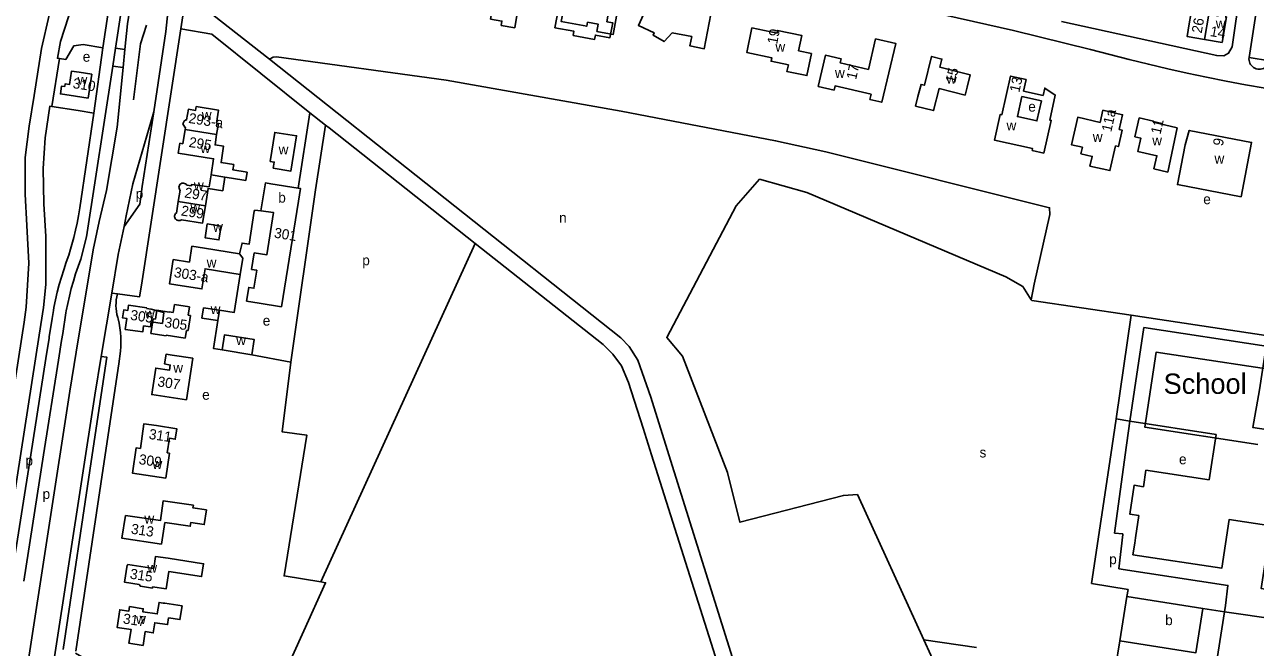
# Model space of a CAD drawing. Extents: x 161093 to 163177, y 379000 to 380904.
# Drawn here: x 161584.6 to 162069, y 380148.5 to 380393.8 of the extents above; entities that cross this region are included whole.
import ezdxf

# ---------------------------------------------------------------- set-up
doc = ezdxf.new("R2010")
doc.units = 0
for name, color, linetype in [('BLT_Basislijn', 7, 'Continuous'), ('BLT_Bebouwing', 7, 'Continuous'), ('BLT_Bebouwing_beschrifting', 7, 'Continuous'), ('BLT_Centroide', 7, 'Continuous'), ('BLT_Huisnummer', 7, 'Continuous'), ('BLT_Huisnummer_reeks', 7, 'Continuous'), ('BLT_Huisnummer_zonder_bebouwing', 7, 'Continuous'), ('BLT_Onderverdeling_panden', 7, 'Continuous'), ('BLT_Plantopo', 7, 'Continuous'), ('BLT_Vlakafsluiter', 7, 'Continuous')]:
    doc.layers.add(name, color=color, linetype=linetype)

msp = doc.modelspace()

# ---------------------------------------------------------------- linework, layer by layer
at = {"layer": 'BLT_Basislijn'}
for p, q in [((162080.1, 380468.07), (162066.51, 380380.82)), ((161680.97, 380380.13), (161648.21, 380405.87)), ((161646.08, 380392.1), (161647.12, 380398.92)), ((161630.58, 380291.16), (161646.08, 380392.1)), ((161640.25, 380391.06), (161635.44, 380359.41)), ((161658.29, 380389.96), (161646.08, 380392.1)), ((161615.35, 380384.6), (161607.68, 380385.93)), ((161615.35, 380384.6), (161611.87, 380358.93)), ((161620.4, 380384.55), (161624.09, 380383.98)), ((162066.51, 380380.82), (162074.57, 380379.45)), ((161619.32, 380377.46), (161623.37, 380376.83)), ((161595.36, 380361.52), (161605.76, 380359.89)), ((161605.76, 380359.89), (161611.87, 380358.93)), ((161635.44, 380359.41), (161630.91, 380329.96)), ((161696.89, 380359.01), (161703.09, 380354.14)), ((161699.16, 380328.7), (161703.09, 380354.14)), ((161629.94, 380323.12), (161630.91, 380329.96)), ((161629.94, 380323.12), (161623.75, 380314.22)), ((161701.22, 380174.31), (161761.99, 380307.55)), ((161602.72, 380305.35), (161602.07, 380303.04)), ((161595.45, 380278.08), (161594.32, 380270.83)), ((161595.93, 380281.17), (161595.45, 380278.08)), ((161600.85, 380280.29), (161599.63, 380272.15)), ((162014.24, 380238.49), (162020.09, 380279.33)), ((162020.09, 380279.33), (162141.64, 380260.89)), ((161599.63, 380272.15), (161599.2, 380269.4)), ((161594.25, 380270.35), (161592.99, 380262.3)), ((161594.32, 380270.83), (161594.25, 380270.35)), ((161599.2, 380269.4), (161597.97, 380261.6)), ((161592.99, 380262.3), (161587.04, 380224.32)), ((161622.35, 380265.14), (161621.68, 380260.21)), ((161674.01, 380263.76), (161689.43, 380260.79)), ((161597.97, 380261.6), (161592.12, 380224.32)), ((161621.68, 380260.21), (161616.31, 380224.32)), ((162012.12, 380224.32), (162014.24, 380238.49)), ((162019.55, 380237.6), (162014.24, 380238.49)), ((162017.76, 380224.32), (162019.55, 380237.6)), ((161587.04, 380224.32), (161579.39, 380175.41)), ((161592.12, 380224.32), (161584.33, 380174.64)), ((161611.25, 380224.32), (161599.79, 380147.76)), ((161616.31, 380224.32), (161604.74, 380147.02)), ((162048.37, 380163.87), (162056.85, 380162.52)), ((162052.58, 380135.03), (162056.85, 380162.52)), ((162056.85, 380162.52), (162057.22, 380165.02)), ((162015.7, 380151.09), (162014.03, 380140.6))]:
    msp.add_line(p, q, dxfattribs=at)
for points in [[(161992.72, 380394.99), (162053.82, 380381.59), (162056.59, 380381.51), (162058.47, 380382.47), (162059.9, 380384.99), (162063, 380407.02), (162073.67, 380475.15), (162080.66, 380484.4)], [(161620.4, 380384.55), (161631.05, 380454.13), (161634.37, 380453.66)], [(161634.37, 380453.66), (161625.11, 380394.11), (161624.09, 380383.98)], [(161588.32, 380365.84), (161591.24, 380384.42), (161594.3, 380397.52), (161598.72, 380409.07), (161603.54, 380421.45), (161606.4, 380431.19), (161606.54, 380431.67)], [(161598.37, 380380.42), (161597.53, 380380.53), (161598.77, 380387.08), (161604.87, 380406.34), (161608.68, 380415.22), (161612.31, 380425.99), (161613.37, 380430.2), (161613.45, 380430.66)], [(161615.35, 380384.6), (161622.03, 380428.24), (161619.18, 380429.82), (161613.45, 380430.66)], [(161790.41, 380429.73), (161841.6, 380420.4), (161892.77, 380409.85), (161973.76, 380391.48), (162004.17, 380383.95)], [(161632.53, 380393.5), (161630.29, 380386.16), (161627.54, 380364.09)], [(161658.29, 380389.96), (161696.89, 380359.01)], [(161607.68, 380385.93), (161603.99, 380385.37), (161600.8, 380380.09), (161598.37, 380380.42)], [(161619.32, 380377.46), (161620.4, 380384.55)], [(161624.09, 380383.98), (161623.37, 380376.83)], [(162004.17, 380383.95), (162011.72, 380381.94), (162019.3, 380380.01), (162026.9, 380378.16), (162034.51, 380376.39), (162042.14, 380374.69), (162049.79, 380373.07), (162057.46, 380371.53), (162065.14, 380370.07), (162072.83, 380368.69), (162080.54, 380367.39), (162088.27, 380366.16), (162096, 380365.02), (162103.74, 380363.95), (162111.5, 380362.96), (162119.27, 380362.05), (162127.04, 380361.23), (162134.82, 380360.48), (162142.61, 380359.81), (162150.41, 380359.22), (162158.21, 380358.71), (162159.21, 380358.65)], [(161598.37, 380380.42), (161595.36, 380361.52)], [(161980.8, 380285.34), (161981.99, 380291.54), (161988.08, 380318.94), (161988.05, 380321.67), (161900, 380343.63), (161880.19, 380348.05), (161819.35, 380359.68), (161750.56, 380371.88), (161683.78, 380381.14), (161682.48, 380380.91), (161680.97, 380380.13)], [(161838.14, 380224.32), (161831.03, 380247.02), (161825.96, 380261.61), (161822.6, 380266.98), (161819.33, 380270.43), (161680.97, 380380.13)], [(162066.51, 380380.82), (162066.48, 380380.25), (162066.52, 380379.68), (162066.65, 380379.12), (162066.85, 380378.59), (162067.13, 380378.09), (162067.47, 380377.63), (162067.88, 380377.23), (162068.33, 380376.88), (162068.83, 380376.6), (162069.37, 380376.4), (162069.92, 380376.27), (162070.49, 380376.22), (162071.06, 380376.24), (162071.62, 380376.35), (162072.17, 380376.54), (162072.68, 380376.8), (162073.15, 380377.13), (162073.56, 380377.52), (162073.92, 380377.96), (162074.22, 380378.45), (162074.44, 380378.98), (162074.57, 380379.45)], [(161606.73, 380301.46), (161609.04, 380310.26), (161619.32, 380377.46)], [(161623.37, 380376.83), (161621.02, 380353.41), (161616.91, 380328.39), (161613.96, 380316.27)], [(161585.47, 380314.7), (161584.83, 380326.98), (161584.89, 380341.43), (161586.42, 380353.78), (161588.32, 380365.84)], [(161570.23, 380142.65), (161590.32, 380271.48), (161592.03, 380282.42), (161592.92, 380291.45), (161593.03, 380310.33), (161592.17, 380323.23), (161591.97, 380337.06), (161592.71, 380349.18), (161594.53, 380361.65), (161595.36, 380361.52)], [(161611.87, 380358.93), (161606.35, 380321.61), (161605.83, 380318.48)], [(161635.44, 380359.41), (161627.27, 380331.07), (161624.65, 380318.51), (161623.75, 380314.22)], [(161696.89, 380359.01), (161692.26, 380329.34)], [(161703.09, 380354.14), (161704.52, 380353.16), (161761.99, 380307.55)], [(161980.8, 380285.34), (161977.44, 380290.66), (161970.78, 380294.44), (161892.43, 380327.72), (161873.9, 380332.87), (161864.63, 380322.42), (161837.37, 380270.61), (161843.59, 380263.22), (161861.27, 380217.43), (161866.15, 380197.81), (161906.85, 380208.4), (161912.38, 380208.69), (161938.5, 380151.53)], [(161699.16, 380328.7), (161689.43, 380260.79)], [(161669.24, 380303.52), (161670.24, 380307.72), (161673, 380307.37), (161674.96, 380320.35), (161675.28, 380320.67), (161677.63, 380320.49)], [(161605.83, 380318.48), (161605.31, 380315.64), (161604.7, 380312.81), (161604.02, 380310), (161603.27, 380307.21), (161602.72, 380305.35)], [(161613.96, 380316.27), (161611.62, 380305.04), (161604.92, 380264.75)], [(161563.68, 380143.64), (161569.99, 380184.41), (161584.44, 380276.56), (161585.22, 380282.45), (161586.24, 380299.89), (161585.47, 380314.7)], [(161623.75, 380314.22), (161621.45, 380303.19), (161618.93, 380288.02)], [(161831.4, 380224.32), (161828.08, 380234.86), (161822.3, 380252.85), (161819.49, 380259.44), (161816.08, 380263.97), (161812.31, 380267.77), (161761.99, 380307.55)], [(161602.07, 380303.04), (161601, 380300.17), (161600, 380297.26), (161599.08, 380294.33), (161598.23, 380291.37), (161597.46, 380288.4), (161596.77, 380285.4), (161596.15, 380282.39), (161595.93, 380281.17)], [(161606.73, 380301.46), (161604.71, 380295.57), (161603.81, 380292.7), (161602.99, 380289.81), (161602.24, 380286.9), (161601.57, 380283.96), (161600.98, 380281.01), (161600.85, 380280.29)], [(161630.58, 380291.16), (161629.9, 380286.58), (161621.15, 380287.73)], [(161661.26, 380281.28), (161667.07, 380280.36), (161669.46, 380295.41)], [(161618.93, 380288.02), (161614.79, 380263.11)], [(161621.15, 380287.73), (161620.88, 380286.59), (161620.7, 380285.43), (161620.59, 380284.26), (161620.57, 380283.09), (161620.62, 380281.92), (161620.76, 380280.76), (161620.97, 380279.61), (161621.27, 380278.47), (161621.43, 380277.94)], [(161980.8, 380285.34), (161981.06, 380285.18), (162020.09, 380279.33)], [(161621.43, 380277.94), (161621.8, 380276.14), (161622.09, 380274.32), (161622.3, 380272.49), (161622.43, 380270.66), (161622.48, 380268.82), (161622.46, 380266.98), (161622.35, 380265.14)], [(161662.34, 380265.68), (161658.99, 380266.18), (161660.65, 380277.26)], [(161614.79, 380263.11), (161612.25, 380247.81), (161591.56, 380113.29), (161571.33, 379981.65), (161565.42, 379943.25)], [(161604.92, 380264.75), (161602.37, 380249.39), (161585.6, 380140.33)], [(161614.79, 380263.11), (161617.01, 380262.79), (161611.25, 380224.32)], [(161689.43, 380260.79), (161686, 380233.37), (161695.69, 380232.11), (161686.73, 380176.66), (161701.22, 380174.31)], [(161882.74, 380057.59), (161870.67, 380100), (161831.4, 380224.32)], [(161899.95, 380091.31), (161888.56, 380085.41), (161886.61, 380085.03), (161884.27, 380084.99), (161882.36, 380085.75), (161880.32, 380088.42), (161877.08, 380100), (161838.14, 380224.32)], [(162018.49, 380168.62), (162018.94, 380171.32), (162004.55, 380173.7), (162012.12, 380224.32)], [(162057.22, 380165.02), (162058.22, 380172.96), (162015.31, 380179.51), (162016.89, 380192.97), (162016.83, 380193.19), (162013.6, 380193.55), (162017.76, 380224.32)], [(161604.59, 380146.24), (161655.66, 380116.98), (161672.91, 380107.27), (161694.48, 380155.01), (161703.07, 380174.01), (161701.22, 380174.31)], [(162076.87, 380151.37), (162077.88, 380159.45), (162056.85, 380162.52)], [(161938.5, 380151.53), (161955.09, 380115.22)], [(161938.5, 380151.53), (161959.26, 380148.52)]]:
    msp.add_lwpolyline(points, dxfattribs=at)
at = {"layer": 'BLT_Bebouwing'}
for p, q in [((161692.26, 380329.34), (161681.48, 380331.08)), ((161645.78, 380328.59), (161645.07, 380324.15)), ((161645.07, 380324.15), (161644.34, 380319.56))]:
    msp.add_line(p, q, dxfattribs=at)
for points in [[(161780.23, 380409.16), (161779.48, 380404.76), (161777.49, 380405.09), (161776.62, 380399.96), (161778.75, 380399.6), (161777.84, 380394.26), (161777.55, 380392.52), (161772.2, 380393.43), (161772.5, 380395.17), (161768.02, 380395.93), (161769.25, 380403.22), (161759.24, 380404.92), (161759.92, 380408.92), (161760.76, 380413.85), (161769.21, 380412.41), (161769.06, 380411.53), (161773.83, 380410.72), (161774.59, 380415.19), (161781.07, 380414.09), (161780.23, 380409.16)], [(161839.43, 380390.57), (161836.32, 380387.06), (161831.95, 380389.65), (161832.38, 380390.56), (161826.21, 380393.44), (161828.21, 380397.72), (161830.44, 380409.21), (161837.61, 380407.82), (161836.09, 380399.83), (161837.52, 380399.51), (161847.35, 380397.66), (161849.01, 380406.11), (161856.01, 380404.78)], [(161817.88, 380398.55), (161818.8, 380403.47), (161810.01, 380405.11), (161809.55, 380402.65), (161806.14, 380403.28), (161806.35, 380404.42), (161797.84, 380406.01), (161796.92, 380401.1), (161795.79, 380395.03), (161805.87, 380393.16), (161806.16, 380394.71), (161810.4, 380393.92), (161809.88, 380391.11), (161816.27, 380389.92), (161817.88, 380398.55)], [(161856.01, 380404.78), (161852.11, 380384.29), (161846.46, 380385.36), (161847.16, 380389.03), (161839.43, 380390.57)], [(162049.02, 380387.92), (162042.12, 380389.12), (162042.98, 380394.05), (162044.32, 380401.47), (162047.48, 380400.92), (162047.05, 380398.47), (162050.73, 380397.83)], [(162050.73, 380397.83), (162054.27, 380397.22), (162054.72, 380399.77), (162057.82, 380399.23), (162057.38, 380396.7), (162057.65, 380396.8), (162055.91, 380386.73), (162049.02, 380387.92)], [(161916.74, 380376.16), (161919.51, 380388.14), (161927.55, 380386.27), (161921.97, 380363.22), (161917.33, 380364.29), (161917.8, 380366.33), (161903.57, 380369.61), (161903.2, 380368.01), (161896.97, 380369.44), (161899.8, 380381.72), (161906.02, 380380.28), (161905.66, 380378.72), (161916.74, 380376.16)], [(161955.55, 380369.15), (161956.76, 380374), (161944.86, 380376.96), (161945.67, 380380.22), (161941.58, 380381.24), (161938.76, 380369.92), (161937.44, 380370.25), (161936.23, 380365.4), (161935.31, 380361.67), (161942.39, 380359.92), (161944.54, 380368.59), (161954.78, 380366.05), (161955.55, 380369.15)], [(161606.1, 380374.99), (161603.09, 380375.45), (161602.28, 380370.16), (161600.54, 380370.43), (161600.39, 380369.41), (161599.18, 380369.59), (161598.7, 380366.49), (161604.67, 380365.58), (161609.61, 380364.83), (161611.04, 380374.24), (161606.1, 380374.99)], [(161985.8, 380343.18), (161981.18, 380344.22), (161981.34, 380344.95), (161966.32, 380348.32), (161968.59, 380358.42), (161969.26, 380358.27), (161972.68, 380373.48), (161978.8, 380372.1), (161977.79, 380367.61), (161985.49, 380365.89), (161986.14, 380368.76), (161990.27, 380366), (161988.06, 380356.17), (161988.69, 380356.03), (161985.8, 380343.18)], [(161660.2, 380350.46), (161660.9, 380354.84), (161660.09, 380354.97), (161660.91, 380360.12), (161652.18, 380361.51), (161651.94, 380360), (161649.07, 380360.45), (161648.4, 380356.22), (161648.13, 380356.26), (161647.43, 380355.75), (161646.95, 380354.76), (161647.62, 380353.33), (161647.91, 380353.28), (161647.78, 380352.46)], [(162034.52, 380335.73), (162029.06, 380337.01), (162030.24, 380342.1), (162022.72, 380343.86), (162023.93, 380349.06), (162021.58, 380349.61), (162023.32, 380357.02)], [(162023.32, 380357.02), (162028.92, 380355.75), (162028.82, 380355.32), (162038.3, 380353.11)], [(161647.78, 380352.46), (161646.89, 380346.85), (161645.72, 380347.03), (161645.1, 380343.12), (161658.98, 380340.92), (161657.98, 380334.63)], [(161663.44, 380333.76), (161666.07, 380333.34), (161671.66, 380332.45), (161672.17, 380335.65), (161666.58, 380336.54), (161666.92, 380338.66), (161661.94, 380339.46), (161662.96, 380345.89), (161659.56, 380346.43), (161660.2, 380350.46)], [(161682.46, 380337.23), (161689.42, 380336.12), (161691.63, 380349.98), (161683.1, 380351.34), (161681.28, 380339.9)], [(162038.3, 380353.11), (162034.52, 380335.73)], [(162063.38, 380325.96), (162038.33, 380330.79), (162041.34, 380346.37), (162042.98, 380352.09), (162067.51, 380347.36), (162063.38, 380325.96)], [(161681.28, 380339.9), (161682.85, 380339.65), (161682.46, 380337.23)], [(161645.71, 380330.79), (161645.52, 380330.46), (161645.41, 380330.09), (161645.38, 380329.71), (161645.42, 380329.33), (161645.55, 380328.97), (161645.74, 380328.64), (161645.78, 380328.59)], [(161648.46, 380330.6), (161648.21, 380330.88), (161647.91, 380331.11), (161647.57, 380331.26), (161647.2, 380331.34), (161646.83, 380331.35), (161646.46, 380331.27), (161646.11, 380331.11), (161645.81, 380330.89), (161645.71, 380330.79)], [(161657.98, 380334.63), (161657.23, 380329.9), (161650.36, 380330.83), (161650.28, 380330.31), (161648.46, 380330.6)], [(161655.77, 380322.45), (161656.85, 380329.27), (161662.58, 380328.36), (161663.44, 380333.76)], [(161681.48, 380331.08), (161679.39, 380331.42), (161677.63, 380320.49)], [(161677.63, 380320.49), (161682.6, 380319.76), (161679.91, 380303.1), (161674.98, 380303.9), (161673.92, 380297.35), (161675.99, 380297.01), (161674.85, 380289.95), (161672.84, 380290.27), (161671.97, 380284.89), (161676.91, 380284.09), (161685.71, 380282.67), (161692.44, 380324.25), (161693.24, 380329.18), (161692.26, 380329.34)], [(161646.38, 380316.9), (161654.68, 380315.6), (161655.77, 380322.45)], [(161644.34, 380319.56), (161644.07, 380319.35), (161643.84, 380319.09), (161643.69, 380318.79), (161643.6, 380318.45), (161643.6, 380318.11), (161643.68, 380317.78), (161643.83, 380317.47), (161644.05, 380317.2), (161644.08, 380317.18)], [(161644.08, 380317.18), (161644.36, 380316.93), (161644.68, 380316.74), (161645.04, 380316.63), (161645.42, 380316.6), (161645.79, 380316.64), (161646.14, 380316.76), (161646.38, 380316.9)], [(161656.52, 380315.32), (161661.97, 380314.46), (161661.11, 380309), (161655.65, 380309.86), (161656.52, 380315.32)], [(161669.24, 380303.52), (161655.42, 380305.72), (161650.48, 380306.5), (161649.49, 380300.25), (161643.14, 380301.25), (161641.63, 380291.75), (161646.57, 380290.97), (161654.4, 380289.72), (161655.66, 380297.61), (161669.46, 380295.41)], [(161669.24, 380303.52), (161670.48, 380301.81), (161669.46, 380295.41)], [(161632.65, 380282.02), (161634.44, 380281.76), (161639.44, 380280.34), (161638.84, 380276.13), (161634.43, 380276.76), (161634.14, 380274.71), (161631.43, 380275.09), (161631.11, 380272.76), (161629.18, 380273.04), (161624.23, 380273.74), (161624.84, 380278.05), (161623.17, 380278.29), (161623.62, 380281.43), (161625.24, 380281.2), (161625.54, 380283.31), (161632.69, 380282.29), (161632.65, 380282.02)], [(161655.02, 380282.23), (161654.41, 380278.2), (161660.65, 380277.26)], [(161661.26, 380281.28), (161655.02, 380282.23)], [(161660.65, 380277.26), (161661.26, 380281.28)], [(162019.55, 380237.6), (162021.39, 380250.01), (162025.13, 380274.47), (162073.2, 380267.11), (162070.58, 380249.99), (162068.08, 380235.11), (162084.57, 380232.59), (162088.01, 380255.45)], [(161662.34, 380265.68), (161663.33, 380271.65), (161674.99, 380269.73), (161674.01, 380263.76)], [(161648.33, 380246), (161650.8, 380262.38), (161642.65, 380263.59), (161640.29, 380263.94), (161639.71, 380260.14), (161641.93, 380259.73), (161641.62, 380257.69), (161636.24, 380258.49), (161634.97, 380250)], [(161674.01, 380263.76), (161662.34, 380265.68)], [(161648.33, 380246), (161634.67, 380248.06), (161634.97, 380250)], [(161640.73, 380225.1), (161641.6, 380230.86), (161643.9, 380230.52), (161644.53, 380234.65), (161636.55, 380235.85), (161631.6, 380236.6), (161630.17, 380226.81)], [(162019.55, 380237.6), (162053.52, 380232.4)], [(162050.77, 380214.46), (162053.52, 380232.4)], [(161630.17, 380226.81), (161628.52, 380227.06), (161627.02, 380217.15), (161640.15, 380215.14)], [(161640.15, 380215.14), (161641.64, 380224.96), (161640.73, 380225.1)], [(162050.77, 380214.46), (162025.93, 380218.26), (162024.94, 380211.79)], [(162023.21, 380200.46), (162019.58, 380201.02), (162021.31, 380212.35), (162024.94, 380211.79)], [(161639.75, 380197.72), (161649.79, 380196.21), (161650.01, 380197.66), (161655.31, 380196.86), (161656.18, 380202.64), (161650.88, 380203.44), (161651.03, 380204.47), (161639.21, 380206.26), (161638.04, 380198.45), (161624.32, 380200.52)], [(161639.75, 380197.72), (161638.46, 380189.18), (161622.94, 380191.52), (161624.32, 380200.52)], [(162023.21, 380200.46), (162021.87, 380191.72), (162021.53, 380189.53), (162020.84, 380185.02), (162055.79, 380179.67), (162058.74, 380198.93), (162075.05, 380196.43), (162071.27, 380171.72), (162104.44, 380166.65), (162109.79, 380201.62)], [(161641.11, 380183.61), (161655.03, 380181.48), (161654.25, 380176.41), (161641.35, 380178.39), (161640.3, 380171.54), (161634.98, 380172.36), (161634.91, 380171.91), (161630.19, 380172.62), (161629.7, 380173.31), (161623.97, 380174.18), (161624.99, 380180.85), (161625.21, 380181.11), (161635.45, 380179.62), (161636.16, 380184.36), (161641.11, 380183.61)], [(161625.94, 380164.58), (161631.3, 380163.77), (161631.12, 380162.58), (161636.8, 380161.72), (161637.53, 380166.22), (161639.13, 380165.98), (161639.83, 380165.88), (161646.58, 380164.86), (161645.76, 380159.45), (161641.29, 380160.12), (161640.9, 380157.5), (161635.86, 380158.26), (161635.25, 380154.24), (161632.07, 380154.78), (161631.24, 380149.33), (161625.7, 380150.18), (161626.52, 380155.63), (161621.01, 380156.39), (161622.07, 380163.38), (161625.68, 380162.83), (161625.94, 380164.58)], [(162015.7, 380151.09), (162018.49, 380168.62)], [(162018.49, 380168.62), (162048.37, 380163.87)], [(162048.37, 380163.87), (162045.58, 380146.34), (162015.7, 380151.09)]]:
    msp.add_lwpolyline(points, dxfattribs=at)
for points in [[(161894.32, 380382.45), (161889.24, 380383.51), (161890.48, 380389.5), (161880.97, 380391.47), (161880.76, 380390.45), (161870.9, 380392.5), (161868.87, 380382.74), (161878.73, 380380.69), (161878.44, 380379.33), (161885.21, 380377.92), (161884.66, 380375.3), (161892.49, 380373.67)], [(161977.15, 380365.46), (161984.79, 380363.75), (161983.01, 380355.85), (161975.38, 380357.56)], [(162008.97, 380360.06), (162007.87, 380355.26), (161999.13, 380357.27), (161996.64, 380346.46), (162000.96, 380345.47), (162000.36, 380342.89), (162004.8, 380341.87), (162003.92, 380338.08), (162011.77, 380336.28), (162013.98, 380345.98), (162015.1, 380345.73), (162016.58, 380352.23), (162015.46, 380352.49), (162016.78, 380358.28)]]:
    msp.add_lwpolyline(points, close=True, dxfattribs=at)
at = {"layer": 'BLT_Onderverdeling_panden'}
for p, q in [((162049.02, 380387.92), (162050.73, 380397.83)), ((161660.2, 380350.46), (161647.78, 380352.46)), ((161663.44, 380333.76), (161657.98, 380334.63)), ((161655.77, 380322.45), (161645.07, 380324.15))]:
    msp.add_line(p, q, dxfattribs=at)
at = {"layer": 'BLT_Plantopo'}
for p, q in [((161643.05, 380280.4), (161643.56, 380283.59)), ((161643.56, 380283.59), (161649.46, 380282.65)), ((161649.46, 380282.65), (161648.93, 380279.33)), ((161634.26, 380272.14), (161635.18, 380277.96)), ((161635.18, 380277.96), (161636.17, 380277.8)), ((161636.17, 380277.8), (161636.72, 380281.26)), ((161636.72, 380281.26), (161641.5, 380280.5)), ((161641.5, 380280.5), (161641.52, 380280.64)), ((161641.52, 380280.64), (161643.05, 380280.4)), ((161648.93, 380279.33), (161649.93, 380279.18)), ((161649.93, 380279.18), (161648.99, 380273.27)), ((161640.32, 380271.18), (161634.26, 380272.14)), ((161648.36, 380273.38), (161647.87, 380270.3)), ((161648.99, 380273.27), (161648.36, 380273.38)), ((161640.37, 380271.5), (161640.32, 380271.18)), ((161647.87, 380270.3), (161640.37, 380271.5))]:
    msp.add_line(p, q, dxfattribs=at)
msp.add_lwpolyline([(161799.05, 380407.16), (161798.36, 380403.48), (161796.96, 380403.74), (161796.22, 380399.8), (161794.75, 380400), (161793.36, 380392.53), (161800.83, 380391.13), (161800.53, 380389.52), (161808.97, 380387.94), (161809.29, 380389.63), (161814.98, 380388.57), (161816.09, 380394.49), (161813.78, 380394.92), (161814.87, 380400.77), (161808.26, 380402.01), (161808.96, 380405.31)], close=True, dxfattribs=at)
msp.add_lwpolyline([(162069.94, 380228.4), (162025.54, 380235.2), (162030, 380264.81), (162087.26, 380256.18), (162082.8, 380226.57)], dxfattribs=at)
at = {"layer": 'BLT_Vlakafsluiter'}
for p, q in [((161642.03, 380408.19), (161640.25, 380391.06)), ((161621.15, 380287.73), (161618.93, 380288.02))]:
    msp.add_line(p, q, dxfattribs=at)

# ---------------------------------------------------------------- texts
at = {"layer": 'BLT_Bebouwing_beschrifting'}
msp.add_text('School', height=8, dxfattribs=at).set_placement((162032.88, 380248.36))
at = {"layer": 'BLT_Centroide'}
for s, p in [('w', (162053.42, 380392.27)), ('w', (161880.11, 380383.09)), ('e', (161607.51, 380379.16)), ('w', (161903.55, 380372.77)), ('w', (161947.41, 380370.56)), ('w', (161605.46, 380370.12)), ('w', (161654.35, 380356.28)), ('e', (161979.63, 380359.5)), ('w', (161971.07, 380352.13)), ('w', (162005.02, 380347.59)), ('w', (162028.41, 380346.23)), ('w', (161653.82, 380343.19)), ('w', (161684.6, 380342.64)), ('w', (162052.91, 380339.03)), ('w', (161651.25, 380328.53)), ('p', (161628.33, 380325.19)), ('b', (161684.45, 380323.67)), ('e', (162048.5, 380323.05)), ('w', (161649.88, 380319.88)), ('n', (161794.98, 380315.74)), ('w', (161658.81, 380312.16)), ('w', (161656.27, 380298.12)), ('p', (161717.51, 380298.99)), ('w', (161657.84, 380279.75)), ('w', (161631.98, 380278.03)), ('e', (161678.35, 380275.23)), ('w', (161667.89, 380267.57)), ('w', (161643.11, 380256.72)), ('e', (161654.51, 380246.04)), ('p', (161584.97, 380220.16)), ('s', (161960.45, 380223.32)), ('e', (162038.95, 380220.64)), ('w', (161634.93, 380218.79)), ('p', (161591.68, 380206.97)), ('w', (161631.76, 380197.28)), ('w', (161632.91, 380177.94)), ('p', (162011.49, 380181.28)), ('w', (161628.5, 380157.78)), ('b', (162033.51, 380157.29))]:
    msp.add_text(s, height=4, dxfattribs=at).set_placement(p)
at = {"layer": 'BLT_Huisnummer'}
for s, rotation, p in [('26', 80.1732, (162047.86, 380390.17)), ('14', 350.1721, (162051, 380389.3)), ('19', 79.2185, (161880.78, 380385.84)), ('17', 77.5671, (161911.87, 380371.88)), ('15', 76.0508, (161950.82, 380370.47)), ('310', 351.361, (161603.38, 380368.8)), ('13', 77.3339, (161976.09, 380366.87)), ('11a', 77.3888, (162012.3, 380351.29)), ('11', 77.146, (162031.66, 380350.32)), ('295', 350.9759, (161649.06, 380345.64)), ('9', 79.0792, (162056.16, 380345.73)), ('297', 350.9691, (161647.33, 380325.75)), ('299', 351.0738, (161646.01, 380318.65)), ('301', 350.8174, (161682.6, 380309.93)), ('305', 351.9185, (161626.05, 380277.54)), ('307', 351.4437, (161636.72, 380251.36)), ('313', 351.4178, (161626.31, 380193.36)), ('315', 351.4238, (161625.88, 380175.64)), ('317', 351.4215, (161623.15, 380157.99))]:
    msp.add_text(s, height=4, rotation=rotation, dxfattribs=at).set_placement(p)
at = {"layer": 'BLT_Huisnummer_reeks'}
for s, rotation, p in [('293-a', 350.9779, (161648.94, 380355.09)), ('303-a', 350.9722, (161643.2, 380294.37)), ('311', 351.4152, (161633.32, 380230.67)), ('309', 351.4152, (161629.37, 380220.75))]:
    msp.add_text(s, height=4, rotation=rotation, dxfattribs=at).set_placement(p)
at = {"layer": 'BLT_Huisnummer_zonder_bebouwing'}
msp.add_text('305', height=4, rotation=351.9185, dxfattribs=at).set_placement((161639.5, 380274.67))

doc.saveas('drawing.dxf')
